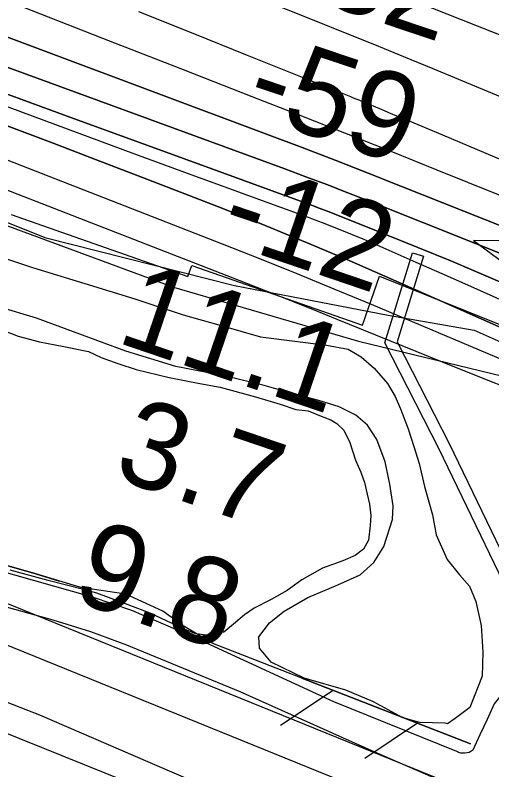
# Model space of a CAD drawing. Extents: x 3704301 to 3742427, y 506229 to 532009.
# Drawn here: x 3710818 to 3711186, y 519474 to 520058 of the extents above; entities that cross this region are included whole.
import ezdxf

# ---------------------------------------------------------------- set-up
doc = ezdxf.new("R2010")
doc.units = 0
for name, color, linetype in [('V-CHAN-DOCK', 7, 'Continuous'), ('V-CHAN-NAID', 7, 'Continuous'), ('V-FLOD-BASE', 7, 'Continuous'), ('V-LEVE-TOET', 7, 'Continuous'), ('V-RIVR-EDGE', 7, 'Continuous'), ('V-RIVR-RANG', 7, 'Continuous'), ('V-ROAD-CNTR', 7, 'Continuous'), ('V-RRAP-FSHR', 7, 'Continuous'), ('V-RRAP-RVMT', 7, 'Continuous'), ('V-SITE-VEGE', 7, 'Continuous'), ('V-SURV-LINE', 7, 'Continuous'), ('V-TOPO-DPTH', 7, 'Continuous'), ('V-TOPO-MAJR', 7, 'Continuous'), ('V-TOPO-MINR', 7, 'Continuous'), ('V-TOPO-SHOR', 7, 'Continuous'), ('V-TOPO-WATR', 7, 'Continuous')]:
    doc.layers.add(name, color=color, linetype=linetype)

msp = doc.modelspace()

# ---------------------------------------------------------------- linework, layer by layer
at = {"layer": 'V-CHAN-DOCK'}
msp.add_lwpolyline([(3711217.36, 519573.96), (3711145.46, 519722.88), (3711103.74, 519804.83), (3711125.09, 519874.42), (3711133.59, 519871.69), (3711113.31, 519805.57), (3711153.41, 519726.81), (3711225.35, 519577.82), (3711217.36, 519573.96)], dxfattribs=at)
at = {"layer": 'V-CHAN-NAID'}
msp.add_lwpolyline([(3711248.78, 519883.43), (3711172.29, 519883.97), (3711233.85, 519838.57)], dxfattribs=at)
at = {"layer": 'V-FLOD-BASE'}
msp.add_lwpolyline([(3711172.66, 519454.74), (3711096, 519488.12), (3710991.9, 519534.67), (3710904.37, 519570.86), (3710876.46, 519581.19), (3710847.6, 519590.1), (3710803.61, 519602.28), (3710782.8, 519608.38), (3710770.5, 519613.08), (3710715.62, 519635.63), (3710627.14, 519671.35), (3710521.15, 519715.05), (3710405.23, 519762.99), (3710297.35, 519806.69), (3710171.97, 519859.33)], dxfattribs=at)
at = {"layer": 'V-LEVE-TOET'}
for points in [[(3710264.46, 519753.42), (3710309.7, 519733.27), (3710355.04, 519713.32), (3710400.47, 519693.58), (3710445.98, 519674.03), (3710491.58, 519654.69), (3710554.03, 519629.37), (3710616.56, 519604.24), (3710679.17, 519579.33), (3710741.87, 519554.61), (3710773.42, 519541.79), (3710805.07, 519529.22), (3710836.82, 519516.89), (3710920.25, 519480.83), (3711001.23, 519445.99), (3711038.07, 519428.64), (3711117.56, 519397.16), (3711209.82, 519359.57), (3711263.28, 519339.37), (3711274.23, 519334.71)], [(3711216.46, 519530.47), (3711202.79, 519533.97), (3711197.11, 519533.95), (3711194.28, 519533), (3711188.15, 519525.42), (3711182.79, 519513.38), (3711177.31, 519501.39), (3711171.69, 519489.46), (3711170.33, 519488.57), (3711168.86, 519487.88), (3711167.3, 519487.41), (3711165.69, 519487.16), (3711164.06, 519487.15), (3711162.45, 519487.37), (3711160.89, 519487.82), (3711159.41, 519488.49), (3711064.3, 519527.02), (3710955.47, 519577.34), (3710908.15, 519597.55), (3710877.87, 519607.88), (3710833.41, 519620.53), (3710786.58, 519633.66)]]:
    msp.add_lwpolyline(points, dxfattribs=at)
at = {"layer": 'V-RIVR-EDGE'}
msp.add_lwpolyline([(3710325.33, 520090.89), (3710457.88, 520041.34), (3710594, 519979.77), (3710728.35, 519931.41), (3710841.1, 519886.1), (3710987.49, 519849.12), (3711106.3, 519826.02), (3711172.91, 519814.44), (3711205.29, 519799.96), (3711233.51, 519804.09), (3711265.93, 519805.21), (3711324.14, 519793.66), (3711376.32, 519773.72), (3711408.66, 519744.82), (3711466.16, 519691.25), (3711522.52, 519662.9), (3711583.7, 519639.33)], dxfattribs=at)
at = {"layer": 'V-ROAD-CNTR'}
msp.add_lwpolyline([(3713157.65, 518919.93), (3712918.69, 518948.16), (3712531.1, 518985.53), (3712067.62, 519029.62), (3711905.97, 519048.2), (3711880.67, 519050.44), (3711857.49, 519053.62), (3711843.39, 519056.88), (3711828.35, 519062.27), (3711804.78, 519068.05), (3711783.56, 519074.25), (3711747.69, 519088.66), (3711454.32, 519226.53), (3711379.46, 519260.43), (3711253.91, 519313.06), (3711117.76, 519371.91), (3710938.02, 519451.49), (3710654.92, 519565.55), (3710319.89, 519704.89), (3710100.18, 519788.97)], dxfattribs=at)
at = {"layer": 'V-RRAP-FSHR'}
for p, q in [((3711063.82, 519535.77), (3711023.19, 519508.69)), ((3711129.03, 519510.33), (3711088.4, 519483.24))]:
    msp.add_line(p, q, dxfattribs=at)
for points in [[(3709741.78, 520362.36), (3710017.65, 520222), (3710534.8, 519997.84), (3710940.37, 519847.89), (3711083.41, 519805.96), (3711220.5, 519772.71), (3711363.54, 519722.11), (3711531.92, 519623.8), (3711655.19, 519570.7), (3711808.33, 519520.01), (3711956.07, 519471.06), (3712143.45, 519424.73), (3712340.74, 519376.66), (3712594.19, 519305.19), (3712920.31, 519227.23), (3713163.79, 519173.07), (3713383.01, 519116.56), (3713629.91, 519034.38)], [(3711169.91, 519494.38), (3710970.89, 519572.03), (3710947.95, 519585.82), (3710932.16, 519597.2), (3710903.75, 519610.22), (3710868.74, 519615.52), (3710833.99, 519625.98), (3710760.08, 519647.13), (3710540.52, 519740.02), (3710203.84, 519882.8), (3710003.29, 519961.04), (3709975.74, 519975.84), (3709949.55, 519986.67), (3709920.09, 519999.48), (3709900.08, 520014.69), (3709879.35, 520025.79), (3709856.94, 520039.82), (3709841.35, 520055.34), (3709824.75, 520071.42)], [(3710273.46, 519853.28), (3710540.52, 519740.02), (3710760.08, 519647.13), (3710833.99, 519625.98), (3710852.37, 519620.45)], [(3711039.75, 519545.16), (3711169.91, 519494.38)]]:
    msp.add_lwpolyline(points, dxfattribs=at)
at = {"layer": 'V-RRAP-RVMT'}
for p, q in [((3710815.02, 519904.05), (3710951.43, 519855.96)), ((3710951.43, 519855.96), (3710954.58, 519864.59)), ((3710954.58, 519864.59), (3711086.44, 519818.3)), ((3711086.44, 519818.3), (3711099.58, 519856.24)), ((3711099.58, 519856.24), (3711228.18, 519804.67))]:
    msp.add_line(p, q, dxfattribs=at)
at = {"layer": 'V-SITE-VEGE'}
msp.add_lwpolyline([(3710721.92, 519899.59), (3710831.42, 519862.98), (3710871.89, 519850.59), (3710910.57, 519838.79), (3710948.06, 519826.39), (3710977.22, 519818.14), (3711007.57, 519809.29), (3711058.73, 519802.87), (3711075.39, 519799.94), (3711085.51, 519794.02), (3711095.64, 519785.12), (3711105.77, 519773.25), (3711111.75, 519763.16), (3711115.93, 519753.65), (3711121.92, 519738.21), (3711126.11, 519724.54), (3711130.31, 519711.46), (3711134.51, 519693.64), (3711140.51, 519671.65), (3711143.52, 519656.19), (3711151.89, 519637.18), (3711161.43, 519625.31), (3711169.19, 519616.41), (3711173.97, 519604.53), (3711178.18, 519586.11), (3711179.42, 519565.3), (3711178.87, 519546.86), (3711169.41, 519522.46), (3711161.1, 519516.49), (3711158.13, 519514.11), (3711152.2, 519509.93), (3711150.41, 519510.52), (3711130.78, 519511.07), (3711117.69, 519514.6), (3711095.07, 519527.04), (3711073.64, 519535.91), (3711041.5, 519545.34), (3711015.9, 519557.77), (3711006.96, 519568.46), (3711006.34, 519577.37), (3711014.64, 519588.1), (3711025.92, 519597.04), (3711044.33, 519607.79), (3711067.5, 519617.36), (3711084.72, 519625.13), (3711095.4, 519634.67), (3711103.1, 519647.18), (3711109.6, 519668.01), (3711110.17, 519678.71), (3711107.75, 519695.36), (3711104.14, 519712.59), (3711097.55, 519729.82), (3711090.39, 519741.1), (3711081.45, 519748.81), (3711068.36, 519755.32), (3711052.88, 519760.04), (3711028.49, 519766.53), (3711010.63, 519771.84), (3710980.88, 519778.9), (3710942.21, 519786.54), (3710903.53, 519798.34), (3710834.49, 519823.74), (3710805.33, 519832.59)], dxfattribs=at)
at = {"layer": 'V-SURV-LINE'}
for points in [[(3709924.11, 519964.01), (3711342.41, 519387.35)], [(3711331.11, 519359.57), (3709912.81, 519936.22)]]:
    msp.add_lwpolyline(points, dxfattribs=at)
at = {"layer": 'V-TOPO-DPTH'}
for points in [[(3711600.22, 519672.11), (3711494.34, 519719.27), (3711437.85, 519744.36), (3711381.33, 519769.36), (3711324.75, 519794.24), (3711268.14, 519819.04), (3711205.13, 519846.55), (3711179.94, 519857.41), (3711154.68, 519868.1), (3711129.33, 519878.54), (3711103.9, 519888.82), (3711067.23, 519903.44), (3711060.07, 519906.25), (3711052.9, 519909.03), (3711045.7, 519911.74), (3711038.48, 519914.4), (3710926.4, 519955.24), (3710863.15, 519978.36), (3710799.94, 520001.58), (3710736.78, 520024.95), (3710673.66, 520048.41), (3710299.22, 520188.05)], [(3710299.22, 520188.05), (3710673.66, 520048.41), (3710736.78, 520024.95), (3710799.94, 520001.58), (3710863.15, 519978.36), (3710926.4, 519955.24), (3711038.48, 519914.4), (3711045.7, 519911.74), (3711052.9, 519909.03), (3711060.07, 519906.25), (3711067.23, 519903.44), (3711103.9, 519888.82), (3711129.33, 519878.54), (3711154.68, 519868.1), (3711179.94, 519857.41), (3711205.13, 519846.55), (3711268.14, 519819.04), (3711324.75, 519794.24), (3711381.33, 519769.36), (3711437.85, 519744.36), (3711494.34, 519719.27), (3711600.22, 519672.11)], [(3710310.51, 520162.05), (3710847.44, 519959.13), (3710880.29, 519946.64), (3710913.11, 519934.06), (3710945.88, 519921.36), (3710978.62, 519908.57), (3711011.25, 519895.5), (3711043.76, 519882.16), (3711076.1, 519868.4), (3711108.31, 519854.36), (3711335.89, 519753.43), (3711416.01, 519719.15), (3711496.69, 519686.29), (3711578.21, 519655.55)], [(3711578.21, 519655.55), (3711496.69, 519686.29), (3711416.01, 519719.15), (3711335.89, 519753.43), (3711108.31, 519854.36), (3711076.1, 519868.4), (3711043.76, 519882.16), (3711011.25, 519895.5), (3710978.62, 519908.57), (3710945.88, 519921.36), (3710913.11, 519934.06), (3710880.29, 519946.64), (3710847.44, 519959.13), (3710310.51, 520162.05)], [(3711606.49, 519729.91), (3711516.37, 519766.09), (3711426.24, 519802.22), (3711336.08, 519838.29), (3711245.9, 519874.31), (3711116.23, 519926.05), (3711090.84, 519936.09), (3711065.41, 519946.03), (3711039.92, 519955.81), (3711014.39, 519965.49), (3710583.72, 520127.24)], [(3711606.49, 519729.91), (3711516.37, 519766.09), (3711426.24, 519802.22), (3711336.08, 519838.29), (3711245.9, 519874.31), (3711116.23, 519926.05), (3711090.84, 519936.09), (3711065.41, 519946.03), (3711039.92, 519955.81), (3711014.39, 519965.49), (3710583.72, 520127.24)], [(3711824.88, 519607.62), (3711402.36, 519787.49), (3711345.43, 519811.48), (3711288.4, 519835.22), (3711231.2, 519858.55), (3711173.89, 519881.62), (3711091.27, 519914.54), (3711075.16, 519920.88), (3711059.02, 519927.13), (3711042.83, 519933.25), (3711026.61, 519939.29), (3710556.81, 520111.76)], [(3710556.81, 520111.76), (3711026.61, 519939.29), (3711042.83, 519933.25), (3711059.02, 519927.13), (3711075.16, 519920.88), (3711091.27, 519914.54), (3711173.89, 519881.62), (3711231.2, 519858.55), (3711288.4, 519835.22), (3711345.43, 519811.48), (3711402.36, 519787.49), (3711824.88, 519607.62)], [(3710443.26, 520066.62), (3710991.04, 519853.25), (3711010.02, 519845.81), (3711028.98, 519838.31), (3711047.9, 519830.73), (3711066.8, 519823.09), (3711157.73, 519786.11), (3711222.22, 519760.3), (3711286.89, 519734.98), (3711351.85, 519710.39), (3711416.99, 519686.28), (3711759.73, 519561.65)]]:
    msp.add_lwpolyline(points, dxfattribs=at)
at = {"layer": 'V-TOPO-MAJR'}
msp.add_lwpolyline([(3710823.26, 520065), (3710885.58, 520040.52), (3710947.93, 520016.12), (3711001.02, 519995.38), (3711036.81, 519981.34), (3711072.58, 519967.21), (3711108.3, 519952.97), (3711143.98, 519938.64), (3711427.06, 519824.46), (3711497.11, 519796.45), (3711567.27, 519768.72)], dxfattribs=at)
at = {"layer": 'V-TOPO-MINR'}
for points in [[(3710299.22, 520188.05), (3710673.66, 520048.41), (3710736.78, 520024.95), (3710799.94, 520001.58), (3710863.15, 519978.36), (3710926.4, 519955.24), (3711038.48, 519914.4), (3711045.7, 519911.74), (3711052.9, 519909.03), (3711060.07, 519906.25), (3711067.23, 519903.44), (3711103.9, 519888.82), (3711129.33, 519878.54), (3711154.68, 519868.1), (3711179.94, 519857.41), (3711205.13, 519846.55), (3711268.14, 519819.04), (3711324.75, 519794.24), (3711381.33, 519769.36), (3711437.85, 519744.36), (3711494.34, 519719.27), (3711600.22, 519672.11)], [(3710304.44, 520176.28), (3710910.32, 519951.09), (3710933.54, 519942.49), (3710956.78, 519933.92), (3710980.03, 519925.41), (3711003.3, 519916.93), (3711044.44, 519901.99), (3711047.14, 519901), (3711049.84, 519899.98), (3711052.53, 519898.94), (3711055.22, 519897.89), (3711068.97, 519892.41), (3711078.51, 519888.55), (3711088.02, 519884.62), (3711097.48, 519880.59), (3711106.92, 519876.49), (3711127.83, 519867.26), (3711147.69, 519858.47), (3711167.53, 519849.65), (3711187.35, 519840.77), (3711207.15, 519831.86), (3711470.99, 519712.69), (3711529.26, 519687.47)], [(3710730.58, 520181.79), (3711050.31, 520053.82), (3711073.01, 520044.68), (3711095.68, 520035.49), (3711118.31, 520026.21), (3711140.92, 520016.88), (3711241.72, 519975.03), (3711314.52, 519944.3), (3711387.07, 519913), (3711459.26, 519880.86), (3711531.19, 519848.14)], [(3710310.51, 520162.05), (3710847.44, 519959.13), (3710880.29, 519946.64), (3710913.11, 519934.06), (3710945.88, 519921.36), (3710978.62, 519908.57), (3711011.25, 519895.5), (3711043.76, 519882.16), (3711076.1, 519868.4), (3711108.31, 519854.36), (3711335.89, 519753.43), (3711416.01, 519719.15), (3711496.69, 519686.29), (3711578.21, 519655.55)], [(3710583.72, 520127.24), (3711014.39, 519965.49), (3711039.92, 519955.81), (3711065.41, 519946.03), (3711090.84, 519936.09), (3711116.23, 519926.05), (3711245.9, 519874.31), (3711336.08, 519838.29), (3711426.24, 519802.22), (3711516.37, 519766.09), (3711606.49, 519729.91)], [(3710556.81, 520111.76), (3711026.61, 519939.29), (3711042.83, 519933.25), (3711059.02, 519927.13), (3711075.16, 519920.88), (3711091.27, 519914.54), (3711173.89, 519881.62), (3711231.2, 519858.55), (3711288.4, 519835.22), (3711345.43, 519811.48), (3711402.36, 519787.49), (3711824.88, 519607.62)], [(3710441.76, 520091.93), (3710532.83, 520055.81), (3710623.95, 520019.81), (3710715.14, 519983.98), (3710806.37, 519948.27), (3710977.99, 519881.29), (3711006.89, 519869.88), (3711035.72, 519858.31), (3711064.46, 519846.5), (3711093.14, 519834.53), (3711215.12, 519783.05), (3711305.06, 519746.04), (3711395.42, 519710.12), (3711486.41, 519675.84), (3711577.82, 519642.65)], [(3711117.15, 520073.11), (3711647.36, 519862.99)], [(3710913.35, 520061.17), (3710955.38, 520044.24), (3710997.41, 520027.32), (3711077.33, 519995.21), (3711079.41, 519994.37), (3711081.49, 519993.53), (3711083.57, 519992.67), (3711085.64, 519991.81), (3711094.76, 519988.01), (3711101.39, 519985.24), (3711108.02, 519982.47), (3711114.65, 519979.69), (3711121.27, 519976.9), (3711148.23, 519965.54), (3711168.35, 519957.08), (3711188.47, 519948.66), (3711208.62, 519940.29), (3711228.77, 519931.94), (3711640.77, 519761.92)]]:
    msp.add_lwpolyline(points, dxfattribs=at)
at = {"layer": 'V-TOPO-SHOR'}
for points in [[(3710802.37, 519816.86), (3710820.35, 519809.82), (3710836.9, 519805.6), (3710855.82, 519801.87), (3710874.73, 519798.13), (3710884.67, 519793.43), (3710897.45, 519788.73), (3710911.64, 519784.04), (3710937.18, 519777.96), (3710960.82, 519773.28), (3710976.43, 519770.49), (3711003.86, 519762.99), (3711022.78, 519757.36), (3711035.08, 519753.14), (3711044.54, 519752.21), (3711054.48, 519747.98), (3711062.04, 519745.16), (3711066.78, 519742.34), (3711071.99, 519737.15), (3711076.74, 519727.71), (3711081.03, 519714.01), (3711085.3, 519704.57), (3711088.16, 519696.54), (3711090.07, 519687.56), (3711091.98, 519680.01), (3711092.95, 519671.03), (3711092.49, 519663.46), (3711091.1, 519652.11), (3711087.34, 519645.02), (3711080.73, 519640.27), (3711071.29, 519636), (3711055.7, 519630.29), (3711039.65, 519621.27), (3711028.33, 519613.2), (3711016.05, 519606.09), (3711002.83, 519599.43), (3710995.28, 519594.22), (3710986.79, 519587.11), (3710979.25, 519580.94), (3710972.63, 519579.51), (3710965.07, 519578.55), (3710957.03, 519579.95), (3710947.57, 519583.7)], [(3710947.57, 519583.7), (3710922.49, 519595.46), (3710901.2, 519603.45), (3710881.33, 519610.96), (3710870.92, 519613.77), (3710843.49, 519620.8), (3710814.16, 519628.76)]]:
    msp.add_lwpolyline(points, dxfattribs=at)
at = {"layer": 'V-TOPO-WATR'}
msp.add_lwpolyline([(3710443.26, 520066.62), (3710991.04, 519853.25), (3711010.02, 519845.81), (3711028.98, 519838.31), (3711047.9, 519830.73), (3711066.8, 519823.09), (3711157.73, 519786.11), (3711222.22, 519760.3), (3711286.89, 519734.98), (3711351.85, 519710.39), (3711416.99, 519686.28), (3711759.73, 519561.65)], dxfattribs=at)

# ---------------------------------------------------------------- texts
at = {"layer": 'V-RIVR-RANG'}
for s, rotation, p in [('-82', 341.45203, (3711023.67, 520078.35)), ('-59', 341.45203, (3710993.38, 519983.03)), ('-12', 341.16833, (3710973.54, 519884.56)), ('-12', 341.16833, (3710973.54, 519884.56)), ('11.1', 341.16833, (3710895.06, 519805.67)), ('11.1', 341.16833, (3710895.06, 519805.67)), ('3.7', 341.16833, (3710892.22, 519700.99)), ('3.7', 341.16833, (3710892.22, 519700.99)), ('9.8', 341.16833, (3710860.18, 519606.26)), ('9.8', 341.16833, (3710860.18, 519606.26))]:
    msp.add_text(s, height=67, rotation=rotation, dxfattribs=at).set_placement(p)

doc.saveas('drawing.dxf')
